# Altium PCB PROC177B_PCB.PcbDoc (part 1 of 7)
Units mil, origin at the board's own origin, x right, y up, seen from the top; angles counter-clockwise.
Board outline 4257.98 x 1561.15 mil, 4 copper layers (Top Layer, Int1 (GND), Int2 (PWR), Bottom Layer), stack 63.572 mil thick; 461 components, 307 nets, 1564 pads, 607 vias.
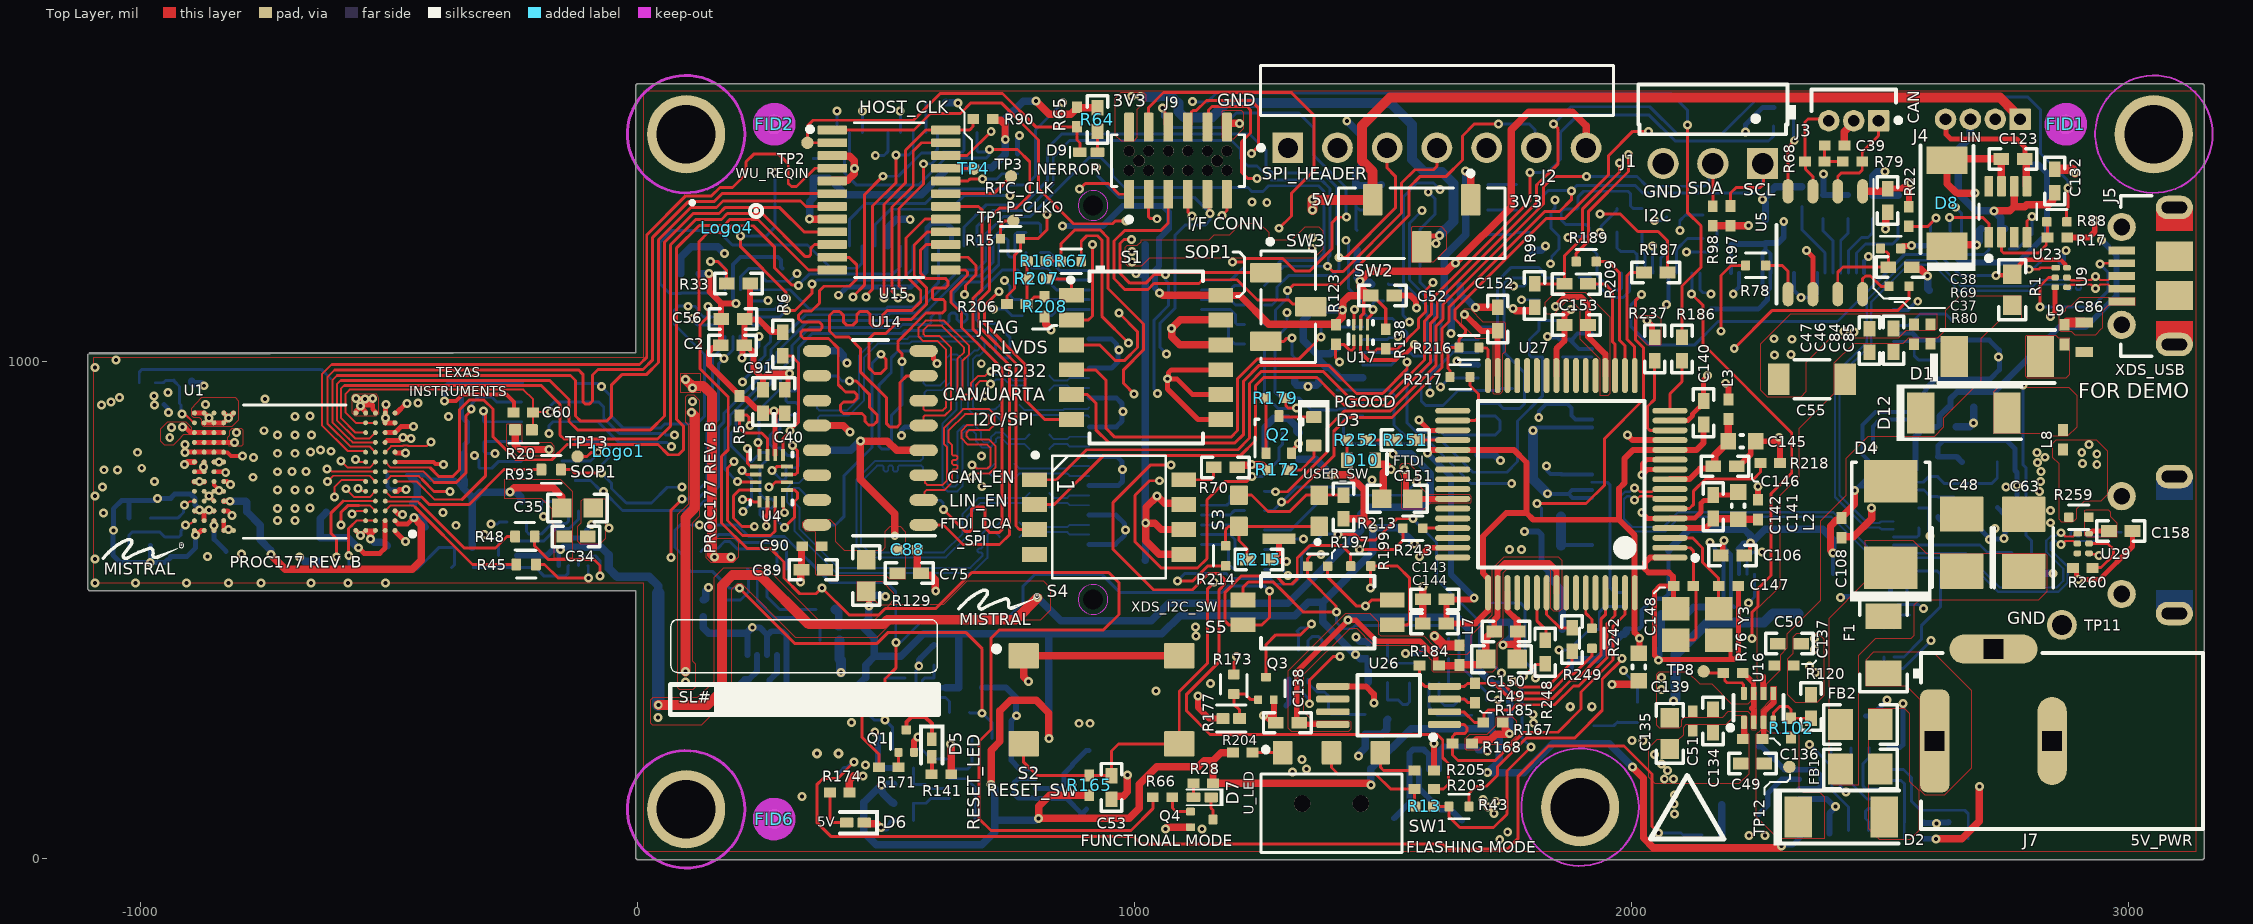
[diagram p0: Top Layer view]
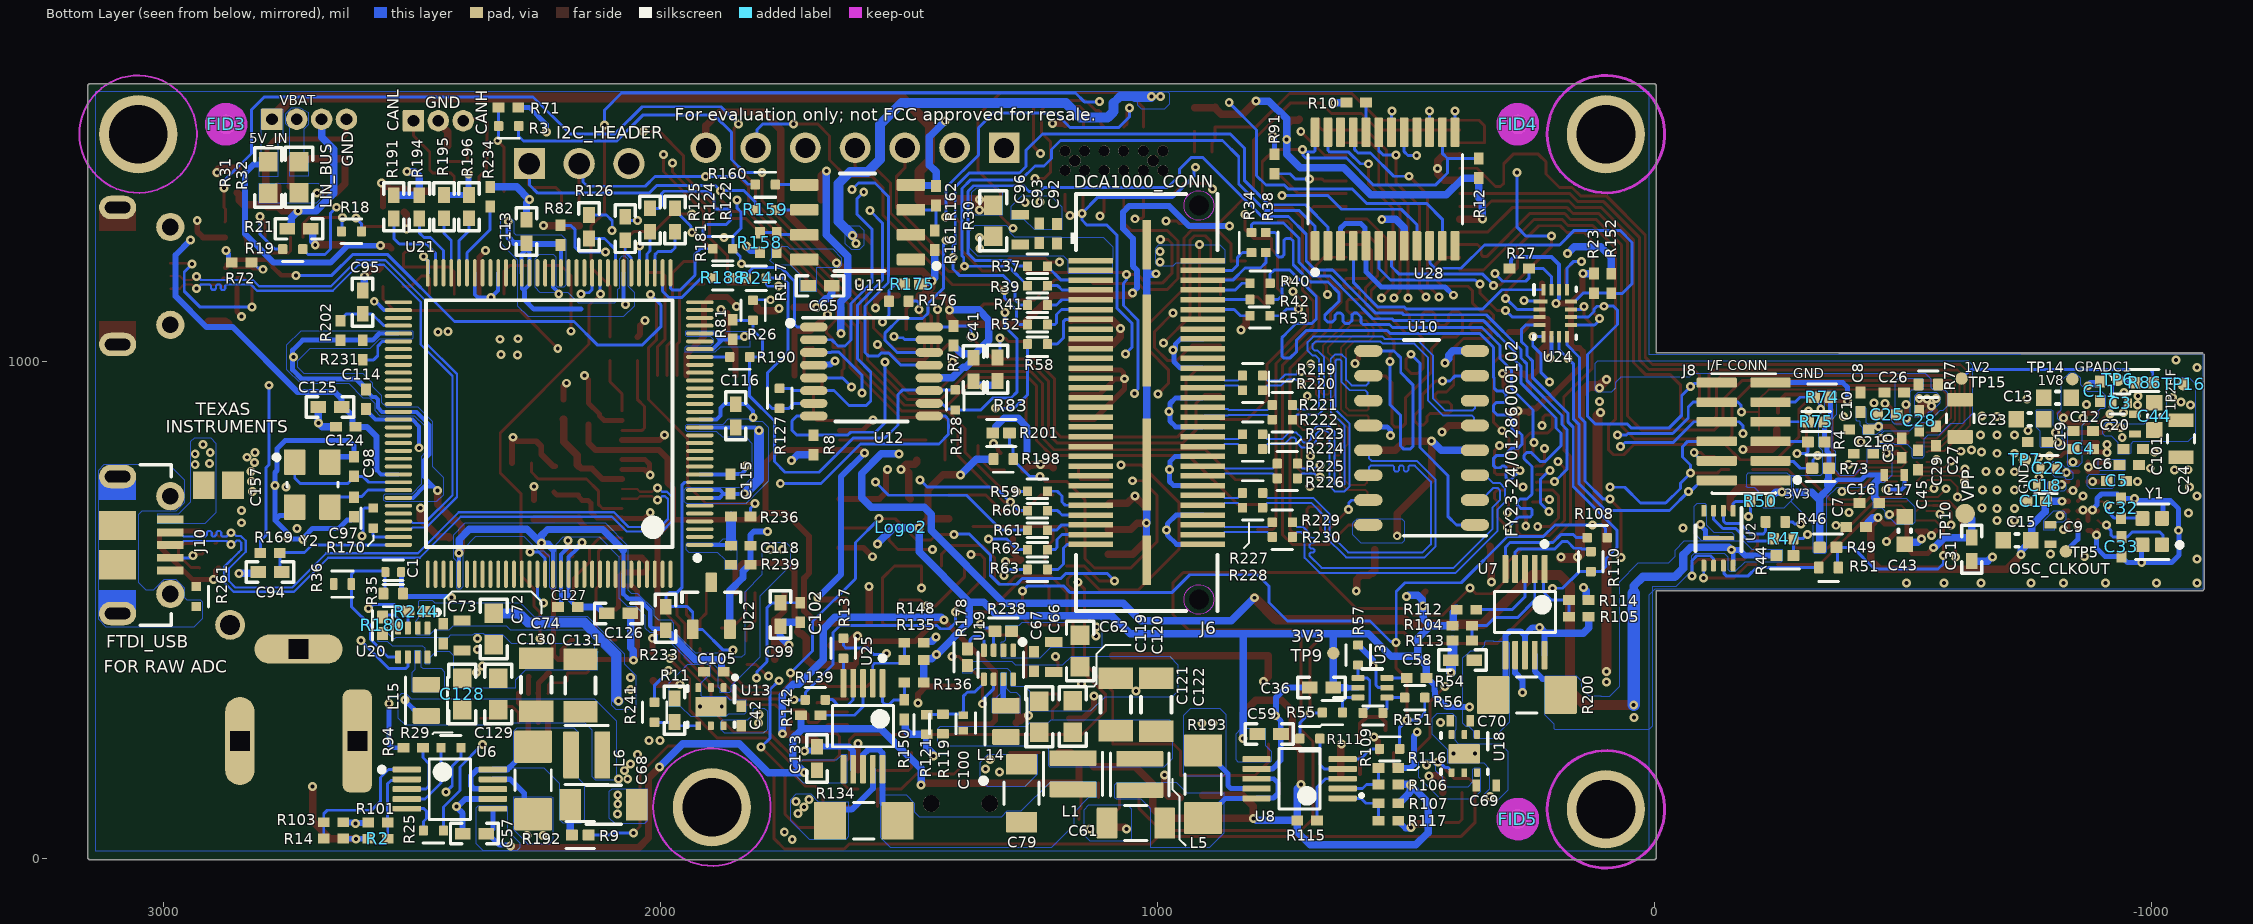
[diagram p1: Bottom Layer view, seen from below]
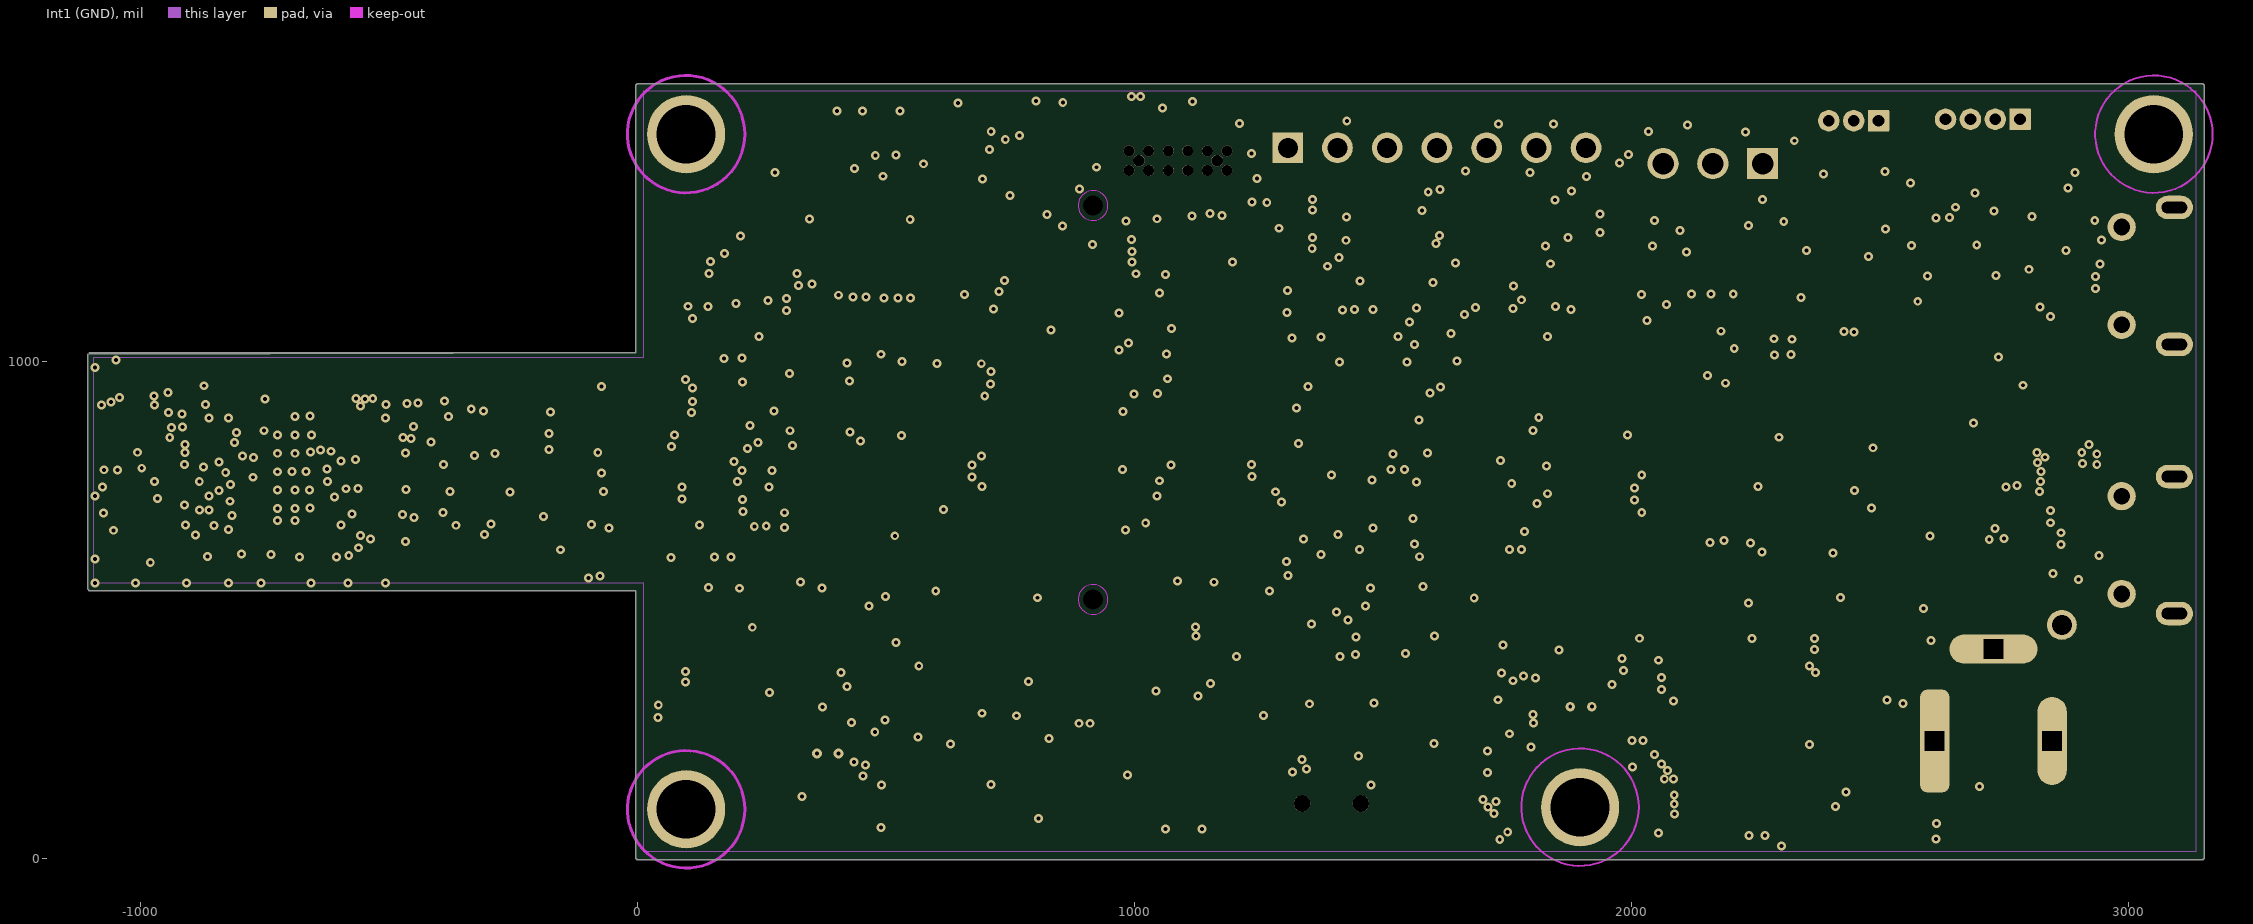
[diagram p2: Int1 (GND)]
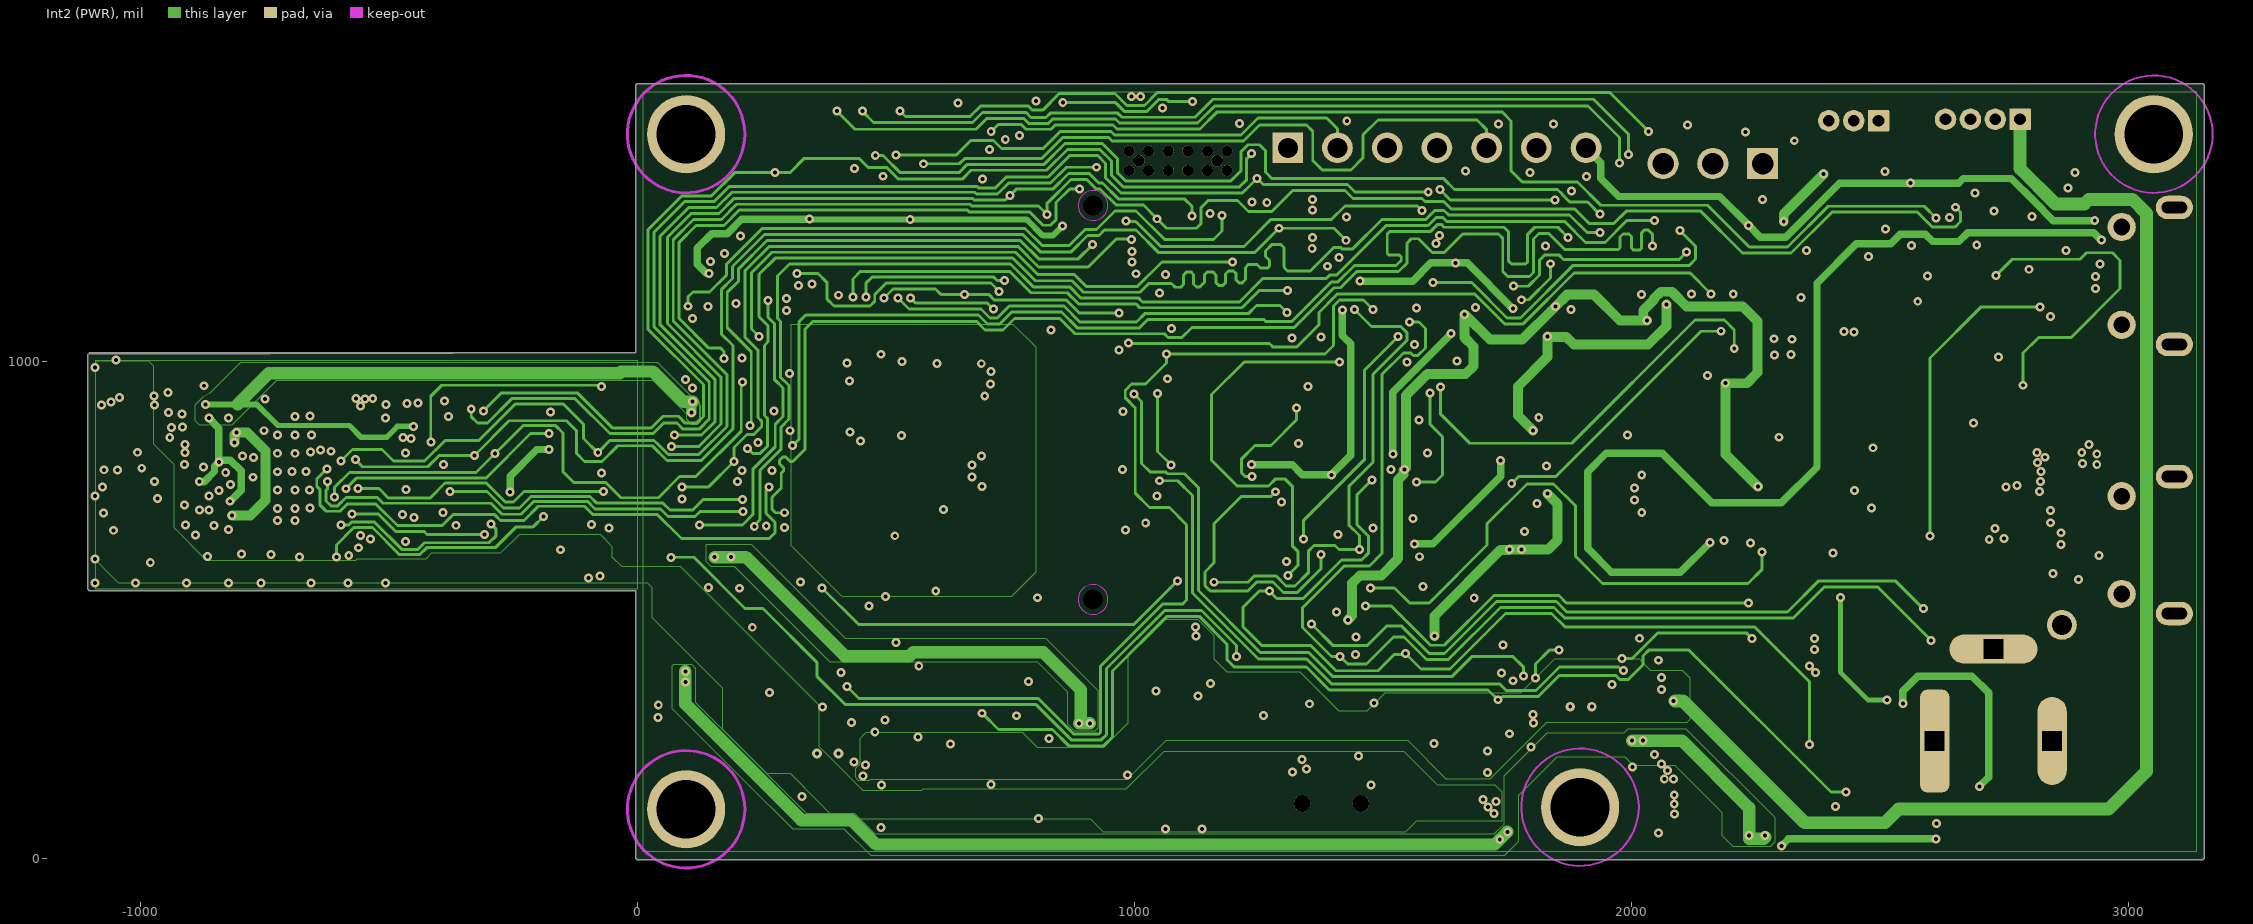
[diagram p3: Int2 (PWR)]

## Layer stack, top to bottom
Top Solder: solder mask 1, Dk 3.5
Top Layer: signal copper 1.85
Dielectric 1: prepreg 1.779, Iteq IT180A Prepreg 106 RC71-NEW, Dk 3.79
Dielectric 2: prepreg 1.779, Iteq IT180A Prepreg 106 RC71-NEW, Dk 3.79
Int1 (GND): signal copper 2.756
Dielectric 3: core 47.244, Iteq IT180A 50 mil core 1/1, Dk 4.28
Int2 (PWR): signal copper 2.756
Dielectric 4: prepreg 1.779, Iteq IT180A Prepreg 106 RC71-NEW, Dk 3.79
Dielectric 5: prepreg 1.779, Iteq IT180A Prepreg 106 RC71-NEW, Dk 3.79
Bottom Layer: signal copper 1.85
Bottom Solder: solder mask 1, Dk 3.5

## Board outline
-1082.65,538.25 -3,538.25 -3.02,0 0,-3.02 3149.61,-3.02 3152.62,0 3152.62,1555.12 3149.49,1558.13 0.14,1558.13 -3.01,1554.89 -3,1016.79 -1082.65,1016.79 -1102.34,1016.79 -3,1016.79 -1105.36,1013.78 -1105.36,541.34 -1102.34,538.24

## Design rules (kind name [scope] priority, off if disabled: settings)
AcuteAngle [All] p0 off: scope1count=1 scope1_0_kind=Board scope1_0_value=Board scope2count=1 scope2_0_kind=Board scope2_0_value=Board commentlength=0 minimum=4.50000000000000E+0001
AcuteAngle [All] p1 off: minimum=4.50000000000000E+0001 checktracksonly=FALSE
AssemblyTestPointUsage [All] p0: scope1count=1 scope1_0_kind=Board scope1_0_value=Board scope2count=1 scope2_0_kind=Board scope2_0_value=Board commentlength=0
AssemblyTestPointUsage [All] p1: valid=2
AssemblyTestpoint [All] p0: scope1count=1 scope1_0_kind=Board scope1_0_value=Board scope2count=1 scope2_0_kind=Board scope2_0_value=Board commentlength=0
BoardOutlineClearance GND_VIA [All] p0 off: scope1count=1 scope1_0_kind=Board scope1_0_value=Board scope2count=1 scope2_0_kind=Board scope2_0_value=Board commentlength=61 gap=2 // Protel DXP Scope 1 Expression Was: IsVia and InNet('GND')
BoardOutlineClearance track_silk [All] p0 off: scope1count=1 scope1_0_kind=Board scope1_0_value=Board scope2count=1 scope2_0_kind=Board scope2_0_value=Board commentlength=90 gap=0 // Protel DXP Scope 1 Expression Was: IsTrack and (OnBottomSilkscreen or OnTopSilkscreen)
BoardOutlineClearance txt [All] p0 off: scope1count=1 scope1_0_kind=Board scope1_0_value=Board scope2count=1 scope2_0_kind=Board scope2_0_value=Board commentlength=89 gap=1 // Protel DXP Scope 1 Expression Was: IsText and (OnBottomSilkscreen or OnTopSilkscreen)
BoardOutlineClearance FAB_TEXT [All] p0 off: scope1count=1 scope1_0_kind=Board scope1_0_value=Board scope2count=1 scope2_0_kind=Board scope2_0_value=Board commentlength=61 gap=0 // Protel DXP Scope 1 Expression Was: WithinRoom('FAB TEXT')
BoardOutlineClearance [All] p0: scope1count=1 scope1_0_kind=Board scope1_0_value=Board scope2count=1 scope2_0_kind=Board scope2_0_value=Board commentlength=0 gap=12
BoardOutlineClearance GND_VIA [IsVia and InNet('GND')] p1: gap=2 ignorepadtopadclearanceinfootprint=FALSE
BoardOutlineClearance track_silk [IsTrack and (OnBottomSilkscreen or OnTopSilkscreen)] p2: gap=0 ignorepadtopadclearanceinfootprint=FALSE
BoardOutlineClearance FAB_TEXT [WithinRoom('FAB TEXT')] p3: gap=0 ignorepadtopadclearanceinfootprint=FALSE
BoardOutlineClearance txt [IsText and (OnBottomSilkscreen or OnTopSilkscreen)] p4: gap=1 ignorepadtopadclearanceinfootprint=FALSE
BoardOutlineClearance [All] p5: gap=12 ignorepadtopadclearanceinfootprint=FALSE except(0: Poly-OutlineEdge)
Clearance Clearance_diff_ext [All] p0 off: scope1count=1 scope1_0_kind=Board scope1_0_value=Board scope2count=1 scope2_0_kind=Board scope2_0_value=Board commentlength=66 gap=6 // Protel DXP Scope 2 Expression Was: OnTopLayer or OnBottomLayer
Clearance BGA_SENSOR [All] p0 off: scope1count=1 scope1_0_kind=Board scope1_0_value=Board scope2count=1 scope2_0_kind=Board scope2_0_value=Board commentlength=59 gap=6 // Protel DXP Scope 1 Expression Was: WithinRoom('sensor')
Clearance "top and bottom" [All] p0 off: scope1count=1 scope1_0_kind=Board scope1_0_value=Board scope2count=1 scope2_0_kind=Board scope2_0_value=Board commentlength=66 gap=6 // Protel DXP Scope 1 Expression Was: OnTopLayer or OnBottomLayer
Clearance "Inner layers" [All] p0 off: scope1count=1 scope1_0_kind=Board scope1_0_value=Board scope2count=1 scope2_0_kind=Net scope2_0_value=GND commentlength=80 gap=6 // Protel DXP Scope 1 Expression Was: OnLayer('L3_SIGNAL 1') OR ('L6_SIGNAL 4')
Clearance Clearance_Keepout [All] p0 off: scope1count=1 scope1_0_kind=Board scope1_0_value=Board scope2count=1 scope2_0_kind=Board scope2_0_value=Board commentlength=48 gap=0 // Protel DXP Scope 1 Expression Was: IsKeepOut
Clearance Same_net [All] p0: scope1count=1 scope1_0_kind=Board scope1_0_value=Board scope2count=1 scope2_0_kind=Board scope2_0_value=Board commentlength=0 gap=0
Clearance Clearance_KO-J5 [All] p0 off: scope1count=1 scope1_0_kind=Board scope1_0_value=Board scope2count=1 scope2_0_kind=Component scope2_0_value=J5 commentlength=60 gap=19.6 // Protel DXP Scope 1 Expression Was: IsKeepOut and IsTrack
Clearance Clearance_BGA [All] p0 off: scope1count=1 scope1_0_kind=Board scope1_0_value=Board scope2count=1 scope2_0_kind=Board scope2_0_value=Board commentlength=57 gap=4 // Protel DXP Scope 1 Expression Was: WithinRoom('BGA1')
Clearance [All] p0: scope1count=1 scope1_0_kind=Board scope1_0_value=Board scope2count=1 scope2_0_kind=Board scope2_0_value=Board commentlength=0 gap=6
Clearance Clearance_Keepout [IsKeepOut] p1: gap=0 ignorepadtopadclearanceinfootprint=TRUE
Clearance BGA_SENSOR [WithinRoom('sensor')] p2: gap=6 ignorepadtopadclearanceinfootprint=TRUE except(0: Text-Hole; 4: Arc-Track Track-Track Track-SMDPad Track-Via; 5: Arc-Arc Arc-SMDPad SMDPad-Via; 5.1: Track-Region SMDPad-SMDPad; 5.6: Via-Region; 7: Arc-Fill Arc-Poly Arc-Region Track-Fill SMDPad-Region THPad-Region; 7.3: Region-Region; 8: SMDPad-Fill SMDPad-Poly THPad-Fill THPad-Poly; 10: Fill-Fill Fill-Poly Fill-Region Poly-Poly Poly-Region; 10.6: Fill-Hole Region-Hole; 11: Poly-Hole; 12: Track-Poly)
Clearance Clearance_diff_ext [InAnyDifferentialPair vs OnTopLayer or OnBottomLayer] p3: gap=6 ignorepadtopadclearanceinfootprint=TRUE except(0: Text-Hole; 4.5: Track-Track; 5: Arc-Arc Arc-Track Arc-SMDPad Track-SMDPad Track-Region; 5.1: SMDPad-SMDPad; 6.2: Region-Region; 7: Arc-Fill Arc-Region Track-Fill; 8: Arc-Poly SMDPad-Fill THPad-Fill Via-Poly Fill-Poly; 10: SMDPad-Poly THPad-Poly Fill-Fill Fill-Region Poly-Region; 11: Fill-Hole Poly-Hole Region-Hole; 12: Track-Poly Poly-Poly)
Clearance [All] p4: gap=6 ignorepadtopadclearanceinfootprint=TRUE except(0: Text-Hole; 5: Arc-Arc Arc-Track Arc-SMDPad Track-SMDPad SMDPad-Region THPad-Region; 5.1: SMDPad-SMDPad; 5.8: Track-Region; 5.9: Via-Region; 6.2: Region-Region; 7: Arc-Fill Arc-Region Track-Fill; 8: Arc-Poly SMDPad-Fill THPad-Fill Via-Poly Fill-Poly; 10: SMDPad-Poly THPad-Poly Fill-Fill Fill-Region Poly-Region; 10.9: Region-Hole; 11: Fill-Hole Poly-Hole; 12: Track-Poly Poly-Poly)
Clearance Clearance_BGA [WithinRoom('BGA1')] p5: gap=4 ignorepadtopadclearanceinfootprint=FALSE except(8: Fill-Fill Fill-Poly Fill-Region Poly-Poly Poly-Region Region-Region; 10: Fill-Hole Poly-Hole Region-Hole)
Clearance "top and bottom" [OnTopLayer or OnBottomLayer] p6: gap=6 ignorepadtopadclearanceinfootprint=TRUE except(5: Arc-Arc Arc-Track Arc-SMDPad Arc-Hole Track-SMDPad Track-Hole SMDPad-Hole THPad-Hole Via-Hole Text-Hole; 5.1: SMDPad-SMDPad; 7: Arc-Fill Arc-Poly Arc-Region Track-Fill Track-Region; 8: Track-Poly SMDPad-Fill SMDPad-Poly SMDPad-Region THPad-Fill THPad-Poly THPad-Region Via-Fill Via-Poly Via-Region Poly-Poly; 10: Fill-Fill Fill-Poly Fill-Region Poly-Region Region-Region; 11: Fill-Hole Poly-Hole Region-Hole)
Clearance Clearance_KO-J5 [IsKeepOut and IsTrack vs InComponent('J5')] p7: gap=19.6 ignorepadtopadclearanceinfootprint=FALSE except(9: SMDPad-SMDPad)
Clearance "Inner layers" [OnLayer('L3_SIGNAL 1') OR ('L6_SIGNAL 4') vs InNet('GND')] p8: gap=6 ignorepadtopadclearanceinfootprint=TRUE except(0: Text-Hole; 5: Arc-Arc Arc-Track Arc-SMDPad Track-Track Track-SMDPad; 5.1: SMDPad-SMDPad; 7: Arc-Fill Arc-Poly Arc-Region Track-Fill Track-Region; 8: SMDPad-Fill SMDPad-Poly SMDPad-Region THPad-Fill THPad-Poly THPad-Region; 10: Fill-Fill Fill-Poly Fill-Region Poly-Region Region-Region; 11: Fill-Hole Poly-Hole Region-Hole; 15: Track-Poly; 20: Poly-Poly)
Clearance Same_net [All] p9: gap=0 ignorepadtopadclearanceinfootprint=TRUE
ComponentClearance ComponentClearance_MatingCon-3D [All] p0 off: scope1count=1 scope1_0_kind=Board scope1_0_value=Board scope2count=1 scope2_0_kind=Board scope2_0_value=Board commentlength=57 gap=0 collisioncheckmode=3 // Protel DXP Scope 2 Expression Was: not InAnyComponent
ComponentClearance "ComponentClearance_WEE Logo" [All] p0: scope1count=1 scope1_0_kind=Component scope1_0_value=Logo4 scope2count=1 scope2_0_kind=Board scope2_0_value=Board commentlength=0 gap=0 collisioncheckmode=3
ComponentClearance ComponentClearance_R77 [All] p0: scope1count=1 scope1_0_kind=Component scope1_0_value=R77 scope2count=1 scope2_0_kind=Component scope2_0_value=Logo1 commentlength=0 gap=0 collisioncheckmode=3
ComponentClearance ComponentClearance_Logo [All] p0: scope1count=1 scope1_0_kind=ComponentClass scope1_0_value=Logo scope2count=1 scope2_0_kind=Board scope2_0_value=Board commentlength=0 gap=0 collisioncheckmode=3
ComponentClearance "ComponentClearance_Mounting Holes_Fiducial Marks" [All] p0: scope1count=1 scope1_0_kind=ComponentClass scope1_0_value=FiducialMark scope2count=1 scope2_0_kind=PadClass scope2_0_value="Mounting Holes PADS" commentlength=0 gap=50 collisioncheckmode=3
ComponentClearance [All] p0: scope1count=1 scope1_0_kind=Board scope1_0_value=Board scope2count=1 scope2_0_kind=Board scope2_0_value=Board commentlength=0 gap=1 collisioncheckmode=3
ComponentClearance ComponentClearance_MatingCon-3D [All vs not InAnyComponent] p1: gap=0 collisioncheckmode=3 verticalgap=0 showdistances=FALSE
ComponentClearance "ComponentClearance_WEE Logo" [InComponent('Logo4')] p2: gap=0 collisioncheckmode=3 verticalgap=0 showdistances=TRUE
ComponentClearance ComponentClearance_R77 [InComponent('R77') vs InComponent('Logo1')] p3: gap=0 collisioncheckmode=3 verticalgap=0 showdistances=TRUE
ComponentClearance ComponentClearance_Logo [InComponentClass('Logo')] p4: gap=0 collisioncheckmode=3 verticalgap=0 showdistances=TRUE
ComponentClearance "ComponentClearance_Mounting Holes_Fiducial Marks" [InComponentClass('FiducialMark') vs InPadClass('Mounting Holes PADS')] p5: gap=50 collisioncheckmode=3 verticalgap=10 showdistances=TRUE
ComponentClearance [All] p6: gap=1 collisioncheckmode=3 verticalgap=10 showdistances=TRUE
DiffPairsRouting 90E [All] p0 off: scope1count=1 scope1_0_kind=Board scope1_0_value=Board scope2count=1 scope2_0_kind=Board scope2_0_value=Board commentlength=69 // Protel DXP Scope 1 Expression Was: InDifferentialPairClass('90E')
DiffPairsRouting 100E [All] p0 off: scope1count=1 scope1_0_kind=Board scope1_0_value=Board scope2count=1 scope2_0_kind=Board scope2_0_value=Board commentlength=70 // Protel DXP Scope 1 Expression Was: InDifferentialPairClass('100E')
DiffPairsRouting 100E [InDifferentialPairClass('100E')] p1: maxlimit=6 minlimit=6 mostfreqgap=6 toplayer_minwidth=4 toplayer_maxwidth=4 toplayer_prefwidth=4 midlayer1_minwidth=4 midlayer1_maxwidth=4 midlayer1_prefwidth=4 midlayer2_minwidth=4 midlayer2_maxwidth=4 midlayer2_prefwidth=4 bottomlayer_minwidth=4 bottomlayer_maxwidth=4 bottomlayer_prefwidth=4 maxuncoupledlength=500
DiffPairsRouting 90E [InDifferentialPairClass('90E')] p2: maxlimit=4.5 minlimit=4.5 mostfreqgap=4.5 toplayer_minwidth=4.5 toplayer_maxwidth=4.5 toplayer_prefwidth=4.5 midlayer1_minwidth=4.5 midlayer1_maxwidth=4.5 midlayer1_prefwidth=4.5 midlayer2_minwidth=4.5 midlayer2_maxwidth=4.5 midlayer2_prefwidth=4.5 bottomlayer_minwidth=4.5 bottomlayer_maxwidth=4.5 bottomlayer_prefwidth=4.5 maxuncoupledlength=500
FabricationTestPointUsage TestPointUsage [All] p0: scope1count=1 scope1_0_kind=Board scope1_0_value=Board scope2count=1 scope2_0_kind=Board scope2_0_value=Board commentlength=0 valid=2 allowmultiple=FALSE
FabricationTestPointUsage TestPointUsage [All] p1: valid=2 allowmultiple=FALSE
FabricationTestpoint Testpoint [All] p0: scope1count=1 scope1_0_kind=Board scope1_0_value=Board scope2count=1 scope2_0_kind=Board scope2_0_value=Board commentlength=0 side=3 testpointundercomponent=TRUE minsize=40 maxsize=100 preferedsize=60 minholesize=0 maxholesize=40 preferedholesize=32 testpointgrid=1
FabricationTestpoint Testpoint [All] p1: side=3 testpointundercomponent=TRUE minsize=40 maxsize=100 preferedsize=60 minholesize=0 maxholesize=40 preferedholesize=32 testpointgrid=1 allowsidetop=TRUE allowsidebottom=TRUE usegrid=TRUE gridtolerance=0.01
FanoutControl Fanout_LCC [All] p0 off: scope1count=1 scope1_0_kind=Board scope1_0_value=Board scope2count=1 scope2_0_kind=Board scope2_0_value=Board commentlength=69 // Protel DXP Scope 1 Expression Was: IsLCC   Fanout_LCC (Default Rule)
FanoutControl Fanout_BGA [All] p0 off: scope1count=1 scope1_0_kind=Board scope1_0_value=Board scope2count=1 scope2_0_kind=Board scope2_0_value=Board commentlength=69 // Protel DXP Scope 1 Expression Was: IsBGA   Fanout_BGA (Default Rule)
FanoutControl Fanout_SOIC [All] p0 off: scope1count=1 scope1_0_kind=Board scope1_0_value=Board scope2count=1 scope2_0_kind=Board scope2_0_value=Board commentlength=71 // Protel DXP Scope 1 Expression Was: IsSOIC   Fanout_SOIC (Default Rule)
FanoutControl Fanout_Default [All] p0: scope1count=1 scope1_0_kind=Board scope1_0_value=Board scope2count=1 scope2_0_kind=Board scope2_0_value=Board commentlength=30 // Fanout_Default (Default Rule)
FanoutControl Fanout_Small [All] p0 off: scope1count=1 scope1_0_kind=Board scope1_0_value=Board scope2count=1 scope2_0_kind=Board scope2_0_value=Board commentlength=84 // Protel DXP Scope 1 Expression Was: (CompPinCount < 5)   Fanout_Small (Default Rule)
FanoutControl Fanout_LCC [IsLCC] p1: bgadir=Out bgaviamode=Centered fanoutstyle=Auto fanoutdirection=Alternating viagrid=1 // Fanout_LCC (Default Rule)
FanoutControl Fanout_BGA [IsBGA] p2: bgadir=Out bgaviamode=Centered fanoutstyle=Auto fanoutdirection=Alternating viagrid=1 // Fanout_BGA (Default Rule)
FanoutControl Fanout_Default [All] p4: bgadir=Out bgaviamode=Centered fanoutstyle=Auto fanoutdirection=Alternating viagrid=1 // Fanout_Default (Default Rule)
FanoutControl Fanout_Small [(CompPinCount < 5)] p5: bgadir=Out bgaviamode=Centered fanoutstyle=Auto fanoutdirection=OutThenIn viagrid=1 // Fanout_Small (Default Rule)
Height Room_Hieght [All] p0 off: scope1count=1 scope1_0_kind=Board scope1_0_value=Board scope2count=1 scope2_0_kind=Board scope2_0_value=Board commentlength=69 // Protel DXP Scope 1 Expression Was: WithinRoom('Room_Hieght 1 MM')
Height Room_Hieght [WithinRoom('Room_Hieght 1 MM')] p1: minheight=0 maxheight=41.34 prefheight=39.37
HoleSize [All] p0: scope1count=1 scope1_0_kind=Board scope1_0_value=Board scope2count=1 scope2_0_kind=Board scope2_0_value=Board commentlength=0 absolutevalues=TRUE maxlimit=280 minlimit=5.9 maxpercent=80.000 minpercent=20.000
HoleSize [All] p1: absolutevalues=TRUE maxlimit=280 minlimit=5.9 maxpercent=80.000 minpercent=20.000
HoleToHoleClearance HoleToHoleClearance_1 [All] p0 off: scope1count=1 scope1_0_kind=Board scope1_0_value=Board scope2count=1 scope2_0_kind=Board scope2_0_value=Board commentlength=57 // Protel DXP Scope 1 Expression Was: WithinRoom('BGA1')
HoleToHoleClearance HoleToHoleClearance_1 [WithinRoom('BGA1')] p1: gap=4 allowstackedmicrovias=FALSE
LayerPairs [All] p0: scope1count=1 scope1_0_kind=Board scope1_0_value=Board scope2count=1 scope2_0_kind=Board scope2_0_value=Board commentlength=0 enforce=TRUE
MatchedLengths DiffPair_MatchedLengths [All] p0 off: scope1count=1 scope1_0_kind=Board scope1_0_value=Board scope2count=1 scope2_0_kind=Board scope2_0_value=Board commentlength=70 tolerance=1000 amplitude=200 gap=20 style=90-Degree // Protel DXP Scope 1 Expression Was: InDifferentialPairClass('100E')
MatchedLengths MatchedLengths_XDSET [All] p0 off: scope1count=1 scope1_0_kind=Board scope1_0_value=Board scope2count=1 scope2_0_kind=Board scope2_0_value=Board commentlength=62 tolerance=2.5 amplitude=200 gap=20 style=90-Degree // Protel DXP Scope 1 Expression Was: InxSignalClass('XDSET')
MatchedLengths MatchedLengths_CAN [All] p0 off: scope1count=1 scope1_0_kind=Board scope1_0_value=Board scope2count=1 scope2_0_kind=Board scope2_0_value=Board commentlength=60 tolerance=2.5 amplitude=200 gap=20 style=90-Degree // Protel DXP Scope 1 Expression Was: InxSignalClass('CAN')
MatchedLengths MatchedLengths_QSPI [All] p0 off: scope1count=1 scope1_0_kind=Board scope1_0_value=Board scope2count=1 scope2_0_kind=Board scope2_0_value=Board commentlength=61 tolerance=200 amplitude=200 gap=20 style=90-Degree // Protel DXP Scope 1 Expression Was: InxSignalClass('QSPI')
MatchedLengths MatchedLengths_RADAR_LVDS [All] p0 off: scope1count=1 scope1_0_kind=Board scope1_0_value=Board scope2count=1 scope2_0_kind=Board scope2_0_value=Board commentlength=67 tolerance=2.5 amplitude=200 gap=20 style=90-Degree // Protel DXP Scope 1 Expression Was: InxSignalClass('RADAR_LVDS')
MatchedLengths MatchedLengths_DCA_T [All] p0 off: scope1count=1 scope1_0_kind=Board scope1_0_value=Board scope2count=1 scope2_0_kind=Board scope2_0_value=Board commentlength=62 tolerance=1000 amplitude=200 gap=20 style=90-Degree // Protel DXP Scope 1 Expression Was: InxSignalClass('DCA_T')
MatchedLengths MatchedLengths_XDS_T [All] p0 off: scope1count=1 scope1_0_kind=Board scope1_0_value=Board scope2count=1 scope2_0_kind=Board scope2_0_value=Board commentlength=62 tolerance=50 amplitude=200 gap=20 style=90-Degree // Protel DXP Scope 1 Expression Was: InxSignalClass('XDS_T')
MatchedLengths MatchedLengths_XDS_DCA_T [All] p0 off: scope1count=1 scope1_0_kind=Board scope1_0_value=Board scope2count=1 scope2_0_kind=Board scope2_0_value=Board commentlength=66 tolerance=5 amplitude=200 gap=20 style=90-Degree // Protel DXP Scope 1 Expression Was: InxSignalClass('XDS_DCA_T')
MatchedLengths MatchedLengths_RADAR_LVDS_DATA [All] p0: scope1count=1 scope1_0_kind=NetClass scope1_0_value=RADAR_LVDS_DATA scope2count=1 scope2_0_kind=Board scope2_0_value=Board commentlength=0 tolerance=5 amplitude=200 gap=20 style=90-Degree
MatchedLengths MatchedLengths_LVDS_D [All] p0: scope1count=1 scope1_0_kind=NetClass scope1_0_value=LVDS_D scope2count=1 scope2_0_kind=Board scope2_0_value=Board commentlength=0 tolerance=5 amplitude=200 gap=20 style=90-Degree
MatchedLengths DiffPair_MatchedLengths [InDifferentialPairClass('100E')] p1: tolerance=1000 checknetsindiffpair=FALSE checkdiffpairvsdiffpair=TRUE checkxsignals=TRUE checkothers=TRUE
MatchedLengths MatchedLengths_LVDS_D [InNetClass('LVDS_D')] p2: tolerance=5 checknetsindiffpair=FALSE checkdiffpairvsdiffpair=TRUE checkxsignals=TRUE checkothers=TRUE
MatchedLengths MatchedLengths_XDS_DCA_T [InxSignalClass('XDS_DCA_T')] p3: tolerance=5 checknetsindiffpair=FALSE checkdiffpairvsdiffpair=TRUE checkxsignals=TRUE checkothers=TRUE
MatchedLengths MatchedLengths_XDSET [InxSignalClass('XDSET')] p4: tolerance=2.5 checknetsindiffpair=FALSE checkdiffpairvsdiffpair=TRUE checkxsignals=TRUE checkothers=TRUE
MatchedLengths MatchedLengths_DCA_T [InxSignalClass('DCA_T')] p5: tolerance=1000 checknetsindiffpair=FALSE checkdiffpairvsdiffpair=TRUE checkxsignals=TRUE checkothers=TRUE
MatchedLengths MatchedLengths_XDS_T [InxSignalClass('XDS_T')] p6: tolerance=50 checknetsindiffpair=FALSE checkdiffpairvsdiffpair=TRUE checkxsignals=TRUE checkothers=TRUE
MatchedLengths MatchedLengths_QSPI [InxSignalClass('QSPI')] p7: tolerance=200 checknetsindiffpair=FALSE checkdiffpairvsdiffpair=TRUE checkxsignals=TRUE checkothers=TRUE
MatchedLengths MatchedLengths_CAN [InxSignalClass('CAN')] p8: tolerance=2.5 checknetsindiffpair=FALSE checkdiffpairvsdiffpair=TRUE checkxsignals=TRUE checkothers=TRUE
MatchedLengths MatchedLengths_RADAR_LVDS_DATA [InNetClass('RADAR_LVDS_DATA')] p9: tolerance=5 checknetsindiffpair=FALSE checkdiffpairvsdiffpair=TRUE checkxsignals=TRUE checkothers=TRUE
MatchedLengths MatchedLengths_RADAR_LVDS [InxSignalClass('RADAR_LVDS')] p10: tolerance=2.5 checknetsindiffpair=FALSE checkdiffpairvsdiffpair=TRUE checkxsignals=TRUE checkothers=TRUE
MinimumAnnularRing MinimumAnnularRing_ThermalPadVias [All] p0 off: scope1count=1 scope1_0_kind=Board scope1_0_value=Board scope2count=1 scope2_0_kind=Board scope2_0_value=Board commentlength=63 minimumring=3.9 // Protel DXP Scope 1 Expression Was: IsVia and InAnyComponent
MinimumAnnularRing [All] p0: scope1count=1 scope1_0_kind=Board scope1_0_value=Board scope2count=1 scope2_0_kind=Board scope2_0_value=Board commentlength=0 minimumring=3.9
MinimumAnnularRing MinimumAnnularRing_ThermalPadVias [IsVia and InAnyComponent] p1: minimumring=3.9
MinimumAnnularRing [All] p2: minimumring=3.9
MinimumSolderMaskSliver MinimumSolderMaskSliver_Logo [All] p0: scope1count=1 scope1_0_kind=ComponentClass scope1_0_value=Logo scope2count=1 scope2_0_kind=ComponentClass scope2_0_value=Logo commentlength=0
MinimumSolderMaskSliver [All] p0: scope1count=1 scope1_0_kind=Board scope1_0_value=Board scope2count=1 scope2_0_kind=Board scope2_0_value=Board commentlength=0
MinimumSolderMaskSliver MinimumSolderMaskSliver_Logo [InComponentClass('Logo') vs InComponentClass('Logo')] p1: minsoldermaskwidth=0.7
MinimumSolderMaskSliver [All] p2: minsoldermaskwidth=3.5
NetAntennae [All] p0: scope1count=1 scope1_0_kind=Board scope1_0_value=Board scope2count=1 scope2_0_kind=Board scope2_0_value=Board commentlength=0
PasteMaskExpansion [All] p0: scope1count=1 scope1_0_kind=Board scope1_0_value=Board scope2count=1 scope2_0_kind=Board scope2_0_value=Board commentlength=0 expansion=0
PlaneClearance [All] p0: scope1count=1 scope1_0_kind=Board scope1_0_value=Board scope2count=1 scope2_0_kind=Board scope2_0_value=Board commentlength=0 clearance=20
PlaneConnect [All] p0: scope1count=1 scope1_0_kind=Board scope1_0_value=Board scope2count=1 scope2_0_kind=Board scope2_0_value=Board commentlength=0 planeconnectstyle=Relief reliefexpansion=10 reliefentries=4 reliefconductorwidth=10 reliefairgap=10
PlaneConnect [All] p1: planeconnectstyle=Relief reliefexpansion=10 reliefentries=4 reliefconductorwidth=10 reliefairgap=10
PolygonConnect [All] p0: scope1count=1 scope1_0_kind=Board scope1_0_value=Board scope2count=1 scope2_0_kind=Board scope2_0_value=Board commentlength=0 connectstyle=Direct reliefconductorwidth=10 reliefentries=4 polygonreliefangle="90 Angle"
PolygonConnect [All] p1: connectstyle=Direct reliefconductorwidth=10 reliefentries=4 polygonreliefangle="90 Angle" airgapwidth=10
RoomDefinition "FAB TEXT" [All] p0 off: scope1count=1 scope1_0_kind=Board scope1_0_value=Board scope2count=1 scope2_0_kind=Board scope2_0_value=Board commentlength=44 region_x1=12378871 region_y1=6167368 region_x2=21198871 region_y2=7897368 confinementstyle=ConfineIn // Protel DXP Scope 1 Expression Was: False
RoomDefinition sensor [All] p0 off: scope1count=1 scope1_0_kind=Board scope1_0_value=Board scope2count=1 scope2_0_kind=Board scope2_0_value=Board commentlength=44 region_x1=4715465 region_y1=21223934 region_x2=16538871 region_y2=25949133 confinementstyle=ConfineIn // Protel DXP Scope 1 Expression Was: False
RoomDefinition "FAB TEXT" [False vs False] p1: confinementstyle=ConfineIn formatcopy=TRUE lockcomponents=FALSE outline -336,-791.4 546,-791.4 546,-964.4 -336,-964.4
RoomDefinition sensor [False vs False] p2: confinementstyle=ConfineIn formatcopy=TRUE lockcomponents=FALSE outline -1102.34,1013.78 80,1013.78 80,541.26 -1102.34,541.26
RoutingCorners [All] p0: scope1count=1 scope1_0_kind=Board scope1_0_value=Board scope2count=1 scope2_0_kind=Board scope2_0_value=Board commentlength=0 cornerstyle=45-Degree minsetback=100 maxsetback=100
RoutingLayers [All] p0: scope1count=1 scope1_0_kind=Board scope1_0_value=Board scope2count=1 scope2_0_kind=Board scope2_0_value=Board commentlength=0 top layer=Automatic mid layer 1=Automatic mid layer 2=Automatic bottom layer=Automatic
RoutingPriority [All] p0: scope1count=1 scope1_0_kind=Board scope1_0_value=Board scope2count=1 scope2_0_kind=Board scope2_0_value=Board commentlength=0
RoutingTopology [All] p0: scope1count=1 scope1_0_kind=Board scope1_0_value=Board scope2count=1 scope2_0_kind=Board scope2_0_value=Board commentlength=0 topology=Shortest
RoutingVias ThermalPadVias [All] p0 off: scope1count=1 scope1_0_kind=Board scope1_0_value=Board scope2count=1 scope2_0_kind=Board scope2_0_value=Board commentlength=63 holewidth=7.87 width=19.68 viastyle="Through Hole" minholewidth=5 minwidth=13 maxholewidth=12.99 maxwidth=23.62 // Protel DXP Scope 1 Expression Was: IsVia and InAnyComponent
RoutingVias [All] p0: scope1count=1 scope1_0_kind=Board scope1_0_value=Board scope2count=1 scope2_0_kind=Board scope2_0_value=Board commentlength=0 holewidth=12.2 width=22.4 viastyle="Through Hole" minholewidth=5.9 minwidth=14 maxholewidth=20 maxwidth=40
RoutingVias ThermalPadVias [IsVia and InAnyComponent] p1: holewidth=7.87 width=19.68 viastyle="Through Hole" minholewidth=5 minwidth=13 maxholewidth=12.99 maxwidth=23.62
RoutingVias [All] p2: holewidth=12.2 width=22.4 viastyle="Through Hole" minholewidth=5.9 minwidth=14 maxholewidth=20 maxwidth=40
ShortCircuit [All] p0: scope1count=1 scope1_0_kind=Board scope1_0_value=Board scope2count=1 scope2_0_kind=Board scope2_0_value=Board commentlength=0 allowed=FALSE
SilkToBoardRegionClearance [All] p0 off: scope1count=1 scope1_0_kind=Board scope1_0_value=Board scope2count=1 scope2_0_kind=Board scope2_0_value=Board commentlength=130 // Protel DXP Scope 1 Expression Was: Not ((IsComment or IsDesignator) And (Hide <> 'False')) and not InRegion(1000,500,4000,800)
SilkToBoardRegionClearance [Not ((IsComment or IsDesignator) And (Hide <> 'False')) and not InRegion(1000,500,4000,800)] p1:
SilkToSilkClearance [All] p0: scope1count=1 scope1_0_kind=Board scope1_0_value=Board scope2count=1 scope2_0_kind=Board scope2_0_value=Board commentlength=0
SilkToSilkClearance [All] p1: silktosilkclearance=3
SilkToSolderMaskClearance SilkToSolderMaskClearance_OutLine [All] p0 off: scope1count=1 scope1_0_kind=Board scope1_0_value=Board scope2count=1 scope2_0_kind=Board scope2_0_value=Board commentlength=65 // Protel DXP Scope 1 Expression Was: istrack and InAnyComponent
SilkToSolderMaskClearance SilkscreenOverComponentPads [All] p0 off: scope1count=1 scope1_0_kind=Board scope1_0_value=Board scope2count=1 scope2_0_kind=Board scope2_0_value=Board commentlength=44 // Protel DXP Scope 1 Expression Was: IsPad
SilkToSolderMaskClearance SilkToSolderMaskClearance_OutLine [istrack and InAnyComponent] p1: minsilkscreentomaskgap=0 clearancetoexposedcopper=FALSE
SilkToSolderMaskClearance SilkscreenOverComponentPads [IsPad] p2: minsilkscreentomaskgap=3 clearancetoexposedcopper=FALSE
SolderMaskExpansion [All] p0: scope1count=1 scope1_0_kind=Board scope1_0_value=Board scope2count=1 scope2_0_kind=Board scope2_0_value=Board commentlength=0 expansion=0
SolderMaskExpansion [All] p1: expansion=0 istentingtop=FALSE
UnRoutedNet [All] p0: scope1count=1 scope1_0_kind=Board scope1_0_value=Board scope2count=1 scope2_0_kind=Board scope2_0_value=Board commentlength=0
UnRoutedNet [All] p1: checkbadconnections=TRUE
UnpouredPolygon [All] p0: scope1count=1 scope1_0_kind=Board scope1_0_value=Board scope2count=1 scope2_0_kind=Board scope2_0_value=Board commentlength=0
Width [All] p0: scope1count=1 scope1_0_kind=Board scope1_0_value=Board scope2count=1 scope2_0_kind=Board scope2_0_value=Board commentlength=0 maxlimit=40 minlimit=4 preferedwidth=5.9
Width [All] p1: maxlimit=40 minlimit=4 preferedwidth=5.9 midlayer1_minwidth=5.9 midlayer2_minwidth=5.9 bottomlayer_minwidth=5.9 minimp=50.000000 maximp=50.000000 favimp=50.000000
12 further rules are at their usual default settings.

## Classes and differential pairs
component class PROC177B_Analog_MUX_SPI: C56 R10 R12 U28
component class PROC177B_I2C_SPI_Connector: J1 J2 J9 mx R83 SW2 SW3
component class PROC177B_FTDI: C138 C139 C140 C141 C142 C143 C144 C145 C146 C147 C148 C149 C150 C151 C152 C153 C157 C158 D10 J10 L2 L3 L7 m mx R99 R167 R168 R184 R185 R186 R187 R189 R209 R216 R217 R218 R237 R242 R243 R248 R249 R251 R252 R259 R260 R261 U26 U27 U29 Y3
net class RADAR_LVDS_DATA: RADAR_LVDS_CLK RADAR_LVDS_DATA0 RADAR_LVDS_DATA1 RADAR_LVDS_DATA2 RADAR_LVDS_DATA3 RADAR_LVDS_FRCLK
net class LVDS_D: LVDS_CLK_RTC_CLKIN_TP LVDS_D0_LIN_PHY_RX LVDS_D1_XDS_UARTA_RX_CAN_RX LVDS_D2_XDS_UARTA_TX_CAN_TX LVDS_D3_nERROR_LED_WD_TP LVDS_FRCLK_HOST_CLK_TP
net class POWER: 3V3_LDO_EN 5V_IN 5V_IN_USB 5V_REG CONN_5V PMIC_CLKOUT PMIC_CLKOUT_LIN_PHY_TX_SOP1 REG_1V2 REG_1V8 REG_OUT_1V2 REG_OUT_1V8 REG_PG REG_RF_1V2 SW_PR1
component class PROC177B_XDS110_Interface: C42 C94 C95 C97 C98 C99 C102 C105 C106 C108 C113 C114 C115 C116 C118 C124 C125 C126 C127 R11 R24 R26 R81 R82 R122 R124 R125 R126 R169 R170 R181 R188 R190 R191 R194 R195 R196 R197 R199 R202 R231 R233 R234 R236 R239 R241 S5 U13 U21 U22 Y2
component class PROC177B_DC_Regulators: C1 C61 C62 C66 C67 C68 C69 C70 C72 C73 C74 C79 C100 C119 C120 C121 C122 C128 C129 C130 C131 L1 L5 L6 L14 L15 Q3 R9 R35 R36 R119 R121 R173 R175 R176 R177 R178 R180 R198 R201 R238 R244 TP9 TP11 U18 U19 U20
net class Regions: 5V_IN 5V_IN_USB GND NetD1_2 NetD2_2 XTALP
component class Logo: Logo1
component class FiducialMark: FID1 FID2 FID3 FID4 FID5 FID6
component class PROC177B_Decoupling_caps_QSPI_Flash_: C4 C5 C6 C7 C8 C9 C10 C11 C12 C13 C14 C15 C16 C17 C18 C19 C20 C21 C22 C23 C24 C25 C26 C27 C28 C29 C30 C34 C35 C44 C45 C101 R44 R45 R46 R47 R48 R49 R50 R51 U2
component class PROC177B_EVM_Hardware: FID1 FID2 FID3 FID4 FID5 FID6 Logo1 Logo2 LOGO3 Logo4 ZZ1 ZZ2 ZZ3 ZZ4 ZZ5
component class Header: J1
component class PROC177B_xWRL6432AoP_Chip: C3 C31 C32 C33 C43 C60 J8 ms R4 R20 R73 R74 R75 R77 R86 R93 TP5 TP6 TP7 TP10 TP13 TP14 TP15 TP16 U1 Y1
component class PROC177B_CAN_LIN_PHY_Interface: C37 C38 C39 C123 C132 D8 J3 J4 R3 R17 R18 R19 R21 R22 R31 R32 R68 R69 R71 R78 R79 R80 R88 U5 U23
component class PROC177B_LVDS_Driver: C75 C88 C89 C90 C91 R90 R91 R129 TP2 TP3 TP4 U10 U14 U15
component class PROC177B_Temp_Current_sensors_EPROM: C36 C57 C58 C59 C65 C133 R2 R14 R25 R29 R54 R55 R56 R57 R94 R97 R98 R101 R103 R104 R105 R106 R107 R108 R109 R110 R111 R112 R113 R114 R115 R116 R117 R134 R135 R136 R137 R139 R142 R148 R150 R151 R157 R158 R159 R160 R161 R162 R192 R193 R200 U3 U6 U7 U8 U11 U25
component class AssemblyNote: ZZ1 ZZ2 ZZ3 ZZ4 ZZ5
component class PROC177B_USB_PWR_DC_Jack_Switch: C46 C47 C48 C49 C50 C51 C55 C63 C84 C85 C86 C134 C135 C136 C137 D1 D2 D3 D4 D6 D12 F1 FB1 FB2 FL1 FL2 J5 J7 L8 L9 LD1 Q2 R1 R72 R76 R102 R120 R172 R174 R179 TP8 TP12 U9 U16
component class PROC177B_DCA1000_Connector_Reset: C52 C53 C92 C93 C96 D5 D7 D9 J6 LD2 LD4 mx Q1 Q4 R28 R30 R34 R37 R38 R39 R40 R41 R42 R52 R53 R58 R59 R60 R61 R62 R63 R64 R65 R66 R123 R138 R141 R165 R171 R213 R214 R215 R219 R220 R221 R222 R223 R224 R225 R226 R227 R228 R229 R230 S2 S3 U17
component class PROC177B_Analog_Mux_SOP_Ctrl: C2 C40 C41 R5 R6 R7 R8 R13 R15 R16 R23 R27 R33 R43 R67 R70 R127 R128 R152 R203 R204 R205 R206 R207 R208 S1 S4 SW1 TP1 U4 U12 U24
differential pair FTDI_USB: +FTDI_USBD_P -FTDI_USBD_N
differential pair CAN: +CANL -CANH
differential pair LVDS_FRCLK: +NetJ6_26 -NetJ6_28
differential pair LVDS_FRCLK_DP8: +RADAR_LVDS_FRCLKP -RADAR_LVDS_FRCLKM
differential pair LVDS_CLK: +NetJ6_46 -NetJ6_44
differential pair LVDS_CLK_DP7: +RADAR_LVDS_CLKP -RADAR_LVDS_CLKM
differential pair LVDS_3: +NetJ6_32 -NetJ6_34
differential pair LVDS_3_DP6: +RADAR_LVDS_3P -RADAR_LVDS_3M
differential pair LVDS_2: +NetJ6_38 -NetJ6_40
differential pair LVDS_2_DP5: +RADAR_LVDS_2P -RADAR_LVDS_2M
differential pair LVDS_1: +NetJ6_50 -NetJ6_52
differential pair LVDS_1_DP4: +RADAR_LVDS_1P -RADAR_LVDS_1M
differential pair LVDS_0: +NetJ6_56 -NetJ6_58
differential pair LVDS_0_DP3: +RADAR_LVDS_0P -RADAR_LVDS_0M
differential pair " ": +XDSET_1_DP -XDSET_1_DM

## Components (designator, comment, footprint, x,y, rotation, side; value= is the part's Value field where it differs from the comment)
C1 "GJM1555C1H100FB01D" FP-GJM1555C1H100FB01D_0402-MFG 2538,575.6 r0 bottom
C2 "C0402C104K8RACTU" 0402 191.79,1032 r0 top
C3 "GRM155C80J105KA12D" FP-GRM155C80J105KA12D_0402-MFG -936.51,915.11 r0 bottom
C4 "CL05B224KO5NNNC" 0402L -861.69,823.27 r0 bottom
C5 "CL05B224KO5NNNC" 0402L -928.89,759.16 r0 bottom
C6 "C1005X7R1H473K050BB" 0402L -954.29,791.28 r180 bottom
C7 "CL05B224KO5NNNC" 0402L -404.95,666.31 r180 bottom
C8 "CL05B224KO5NNNC" 0402L -413.7,917.2 r270 bottom
C9 "GRM155C81C225KE11D" 0402S -796.05,651.26 r90 bottom
C10 "CL05B224KO5NNNC" 0402L -410.75,862.73 r180 bottom
C11 "CL05B224KO5NNNC" 0402L -895.64,939.59 r270 bottom
C12 "CL05B224KO5NNNC" 0402L -861.75,859.54 r0 bottom
C13 "GRM188C81A106MA73D" 0603L -809.83,926.37 r0 bottom
C14 "CL05B224KO5NNNC" 0402L -767.2,718.18 r180 bottom
C15 "GRM188C81A106MA73D" 0603L -728.49,639.33 r0 bottom
C16 "CL05B224KO5NNNC" 0402L -431.54,714.38 r180 bottom
C17 "GRM155C81C225KE11D" 0402S -481.85,770.72 r0 bottom
C18 "GRM155C80J105KA12D" FP-GRM155C80J105KA12D_0402-MFG -783.92,748.92 r180 bottom
C19 "CL05B224KO5NNNC" 0402L -769.73,837.09 r180 bottom
C20 "GRM155C81C225KE11D" 0402S -965.93,873.42 r270 bottom
C21 "CL05B224KO5NNNC" 0402L -419.92,813.77 r180 bottom
C22 "GRM155C80J105KA12D" FP-GRM155C80J105KA12D_0402-MFG -791.25,784.21 r180 bottom
C23 "GRM188C81A106MA73D" 0603L -754.48,882.83 r0 bottom
C24 "GRM21BR71C475KE51L" FP-GRM21BR71C475KE51L_0805-MFG -1058.5,843.8 r90 bottom
C25 "CL05B224KO5NNNC" 0402L -466.71,892.5 r180 bottom
C26 "CL05B224KO5NNNC" 0402L -481.51,937 r180 bottom
C27 "GRM21BR71C475KE51L" FP-GRM21BR71C475KE51L_0805-MFG -614.09,884.93 r90 bottom
C28 "CL05B224KO5NNNC" 0402L -531.9,880.26 r270 bottom
C29 "CL05B224KO5NNNC" 0402L -565.75,849.51 r90 bottom
C30 "C0402C103K4RACTU" 0402L -496.85,825.26 r270 bottom
C31 "C1005X7R1H104K050BE" 0402 -637.54,621.5 r270 bottom
C32 "GJM1555C1H4R7BB01D" 0402L -937.91,703.76 r270 bottom
C33 "GJM1555C1H4R7BB01D" 0402L -938.64,626.35 r90 bottom
C34 "C1005X7R1H104K050BE" 0402 -123.28,647.05 r0 top
C35 "CL10B105KO8NFNC" 0603 -119.98,704.58 r180 top
C36 "GCM155R71H104KE02D" 0402 670.48,343.24 r0 bottom
C37 "C0402C104K8RACTU" 0402 2540.57,1189.11 r180 top
C38 "C0402C104K8RACTU" 0402 2515.6,1323.38 r90 top
C39 "GCM155R71H472KA37D" 0402L 2409,1433.6 r180 top
C40 "C0402C104K8RACTU" 0402 296.84,918.94 r90 top
C41 "C0402C104K8RACTU" 0402 1370.83,983.24 r270 bottom
C42 "C1005X7S1A225K050BC" 0402_065L 1837.69,286.05 r90 bottom
C43 "GRM188C81A106MA73D" 0603L -502.75,659.1 r270 bottom
C44 "GRM188C81A106MA73D" 0603L -1004.41,889.04 r90 bottom
C45 "C0402C103K4RACTU" 0402L -529.26,801.31 r270 bottom
C46 "GRM155R61A106ME11D" 0402 2527.55,1042.09 r270 top
C47 "GRM155R61A106ME11D" 0402 2479.01,1041.64 r90 top
C48 "T491B476K010AT" 3528-21 2664.63,634.94 r90 top
C49 "GCM155R71H104KE02D" 0402 2243.72,190.48 r180 top
C50 "GCM155R71H104KE02D" 0402 2317.97,431.63 r180 top
C51 "GRT155C81A105KE01D" 0402L 2123.57,276.24 r270 top
C52 "GCM155R71H104KE02D" 0402 1499.21,1131.87 r180 top
C53 "GCM155R71H104KE02D" 0402 954,142.6 r270 top
C55 "GRM31CR61A476KE15L" 1206_180 2363.38,963.49 r180 top
C56 "GCM155R71H104KE02D" 0402 192.53,1084.61 r0 top
C57 "GCM155R71H104KE02D" 0402 2374.77,49.43 r0 bottom
C58 "GCM155R71H104KE02D" 0402 386.7,398.47 r0 bottom
C59 "GCM155R71H104KE02D" 0402 775.79,249.69 r180 bottom
C60 "CL05B224KO5NNNC" 0402L -228.99,896.44 r0 top
C61 "GRM31CR70J226ME19K" FP-GRM31CR70J226ME19K_1206-MFG 1044.03,70.8 r180 bottom
C62 "GRM188C81A106MA73D" 0603 1156.35,416.75 r270 bottom
C63 "T491B476K010AT" 3528-21 2789.33,634.39 r90 top
C65 "GCM155R71H104KE02D" 0402 1679.36,1151.54 r180 bottom
C66 "GRM188R71C474KA88D" 0603S 1208.99,404.57 r270 bottom
C67 "GRM1555C1H471JA01D" 0402L 1248.84,395.61 r270 bottom
C68 "GRM31CR60J476ME19L" 1206_180 2114.72,107.45 r0 bottom
C69 "GRM155C81C225KE11D" 0402S 339.16,146.27 r0 bottom
C70 "GRM155C81C225KE11D" 0402S 391.76,276.58 r180 bottom
C72 "GRM188C81A106MA73D" 0603 2335.86,460.98 r270 bottom
C73 "GRM188R71C474KA88D" 0603S 2399.71,448.21 r270 bottom
C74 "GRM1555C1H471JA01D" 0402L 2437.19,451.83 r270 bottom
C75 "GCM155R71H104KE02D" 0402 547.26,573.55 r0 top
C79 "GRM31CR70J226ME19K" FP-GRM31CR70J226ME19K_1206-MFG 1274,130.6 r270 bottom
C84 "GCM155C71A474KE36D" 0402L 2568.88,1053.8 r90 top
C85 "GCM155R71C224KE02D" 0402L 2601.76,1054.73 r270 top
C86 "GRT188R61A106KE13D" 0603S 2910.89,1048.17 r90 top
C88 "GCM155R71E103KA37D" 0402L 543.72,620.74 r0 top
C89 "GCM155R71H104KE02D" 0402 354.19,580.27 r180 top
C90 "GCM155R71E103KA37D" 0402L 351.56,627.8 r180 top
C91 "GCM155R71H104KE02D" 0402 253.09,918.94 r90 top
C92 "GCM155C71A474KE36D" 0402L 1202.77,1256.36 r90 bottom
C93 "GRT155C81A105KE01D" 0402L 1238.41,1257.18 r90 bottom
C94 "C0402C104K8RACTU" 0402 2786,575.6 r0 bottom
C95 "C0402C104K8RACTU" 0402 2599.45,1118.65 r270 bottom
C96 "GRT188R61A106KE13D" 0603S 1276.77,1264.52 r270 bottom
C97 "CC0402DRNPO9BN8R0" 0402L 2616.98,706.75 r90 bottom
C98 "CC0402DRNPO9BN8R0" 0402L 2616.98,787.95 r270 bottom
C99 "C0402C104K8RACTU" 0402 1759.12,490.29 r90 bottom
C100 "GJM1555C1H100FB01D" FP-GJM1555C1H100FB01D_0402-MFG 1391.2,272.06 r90 bottom
C101 "CL05B224KO5NNNC" 0402L -962.32,823.13 r0 bottom
C102 "GCM155R71E103KA37D" 0402L 1719.12,494.23 r90 bottom
C105 "C1005X7S1A225K050BC" 0402_065L 1893.01,375.07 r180 bottom
C106 "C0402C104K8RACTU" 0402 2203.44,608.87 r0 top
C108 "GRT155C81A105KE01D" 0402L 2423,664.6 r270 top
C113 "C0402C104K8RACTU" 0402 2269.89,1260.99 r270 bottom
C114 "GRT155C81A105KE01D" 0402L 2592.89,923.38 r270 bottom
C115 "GCM155R71E103KA37D" 0402L 1859.31,752.89 r90 bottom
C116 "C0402C104K8RACTU" 0402 1848.96,890 r270 bottom
C118 "GCM155R71E103KA37D" 0402L 1839,628.6 r0 bottom
C119 "GRM188C81A106MA73D" 0603 1238.56,284.57 r90 bottom
C120 "GRM188C81A106MA73D" 0603 1170.74,285.07 r90 bottom
C121 "C3216X6S1A226M160AB" 1206_180L 1084.38,309.27 r270 bottom
C122 "C3216X6S1A226M160AB" 1206_180L 1003.13,309 r270 bottom
C123 "GCM155R71H104KE02D" 0402 2768,1406.74 r0 top
C124 "C1005X7S1A225K050BC" 0402_065L 2633.47,868.02 r180 bottom
C125 "C0402C104K8RACTU" 0402 2665.14,907.54 r180 bottom
C126 "C0402C104K8RACTU" 0402 2085.08,492.65 r0 bottom
C127 "GRT155C81A105KE01D" 0402L 2186.69,505.45 r0 bottom
C128 "GRM188C81A106MA73D" 0603 2398.91,330.26 r90 bottom
C129 "GRM188C81A106MA73D" 0603 2326.75,330.26 r90 bottom
C130 "C3216X6S1A226M160AB" 1206_180L 2250.46,348.82 r270 bottom
C131 "C3216X6S1A226M160AB" 1206_180L 2161.46,347.44 r270 bottom
C132 "885012005063" 0402 2851.75,1362.4 r90 top
C133 "GCM155R71H104KE02D" 0402 1685.69,200.71 r90 bottom
C134 "GCM155R71H104KE02D" 0402 2164.38,276.25 r270 top
C135 "GRM188Z71A106MA73D" 0603 2077.15,251.31 r270 top
C136 "GRT155C81A105KE01D" 0402L 2244,239.6 r180 top
C137 "GRT155C81A105KE01D" 0402L 2307,387.6 r0 top
C138 "C0402C104K8RACTU" 0402 1308,272.6 r180 top
C139 "C1608X7S1A475K080AC" 0603L 2015.1,384.8 r270 top
C140 "C0402C104K8RACTU" 0402 2145.41,896.26 r90 top
C141 "C1608X7S1A475K080AC" 0603L 2214.74,709.19 r90 top
C142 "C0402C104K8RACTU" 0402 2164.74,707.22 r270 top
C143 "C0402C104K8RACTU" 0402 1604.4,520.77 r180 top
C144 "C0402C104K8RACTU" 0402 1604.25,472.34 r180 top
C145 "C1608X7S1A475K080AC" 0603L 2222.39,838.85 r0 top
C146 "C0402C104K8RACTU" 0402 2188.53,788.54 r180 top
C147 "GCM1555C1H8R0DA16D" 0402L 2195.43,547.51 r0 top
C148 "GCM1555C1H8R0DA16D" 0402L 2104.92,547.51 r180 top
C149 "GCM188R71C105KA64D" 0603 1738.57,400.73 r180 top
C150 "C0402C104K8RACTU" 0402 1747.8,456.06 r0 top
C151 "GCM188R71C105KA64D" 0603 1529.11,723.04 r0 top
C152 "C0402C104K8RACTU" 0402 1731.16,1084.69 r90 top
C153 "C0402C104K8RACTU" 0402 1889.06,1072.47 r180 top
C157 "CL21B106KOQNNNE" 0805L 2889.83,750.46 r180 bottom
C158 "C0402C104K8RACTU" 0402 2984.65,658.22 r0 top
D1 "PMEG3020EP,115" SOD-128 2736.44,1009.5 r0 top
D2 "PMEG3020EP,115" SOD-128 2422.41,83.16 r0 top
D3 "TLMY1000-GS08" TLMx1000_Yellow 1361.24,858.87 r90 top
D4 "SZP6SMB6.8AT3G" SMB 2522,671.6 r90 top
D5 "APHHS1005CGCK" APHHS1005_Green 592.69,221.68 r90 top
D6 "APHHS1005CGCK" APHHS1005_Green 439.08,71.69 r0 top
D7 "APHHS1005CGCK" APHHS1005_Green 1136.94,122.48 r0 top
D8 "PMEG3020EP,115" SOD-128 2635,1317.6 r90 top
D9 "APHHS1005SURCK" APHHS1005_Red 908.35,1420.33 r180 top
D10 "TLMY1000-GS08" TLMx1000_Yellow 1456.4,800.77 r0 top
D12 "PMEG3020EP,115" SOD-128 2668.99,896.02 r0 top
F1 "32V, 5A" 1206 2507.4,429.46 r270 top
FB1 "BLM21PG300SH1D" 0805_HV 2460.75,179.55 r0 top
FB2 "BLM21PG300SH1D" 0805_HV 2460.75,269.12 r0 top
FID1 "Fiducial" Fiducial10-20 2874.02,1476.38 r90 top locked
FID2 "Fiducial" Fiducial10-20 275.58,1476.39 r90 top locked
FID3 "Fiducial" Fiducial10-20 2874.02,1476.38 r180 bottom locked
FID4 "Fiducial" Fiducial10-20 275.58,1476.39 r90 bottom locked
FID5 "Fiducial" Fiducial10-20 275.59,78.74 r180 bottom locked
FID6 "Fiducial" Fiducial10-20 275.59,78.74 r90 top locked
J1 "61300311021" Wurth_61300311021 2163.91,1397.45 r180 top locked
J2 "0022288072" FP-0022288072_HDR7-MFG 1608.83,1544.36 r0 top locked
J3 "M50-3930342" FP-M50-3930342_HDR3-MFG 2447.23,1522.93 r180 top
J4 "M50-3930442" FP-M50-3930442_HDR4-Recommended_Land_Pattern 2707.04,1525.96 r180 top
J5 "105017-0001" CONN_105017-0001 3039.37,1171.38 r90 top
J6 "QSH-030-01-L-D-A" Samtec_QSH-030-01-X-D-A 1022.21,916.8 r180 bottom locked
J7 "PJ-002AH" CUI_PJ-002AH 2728.35,235.81 r0 top
J8 "BC050-12A-K0-0200-0160-0480-LB" FP-BC050-12A-K0-0200-0160-0480-LB_HDR12-MFG -178.72,858.45 r90 bottom
J9 "BC084-12-A-0390-L-C" FP-BC084-12-A-0390-L-C_CONN_RCPT12-MFG 1088.05,1403.29 r0 top locked
J10 "105017-0001" CONN_105017-0001 3039.37,629.99 r270 bottom locked
L1 "LQM2MPZR10MJHL" "FP-LQM2MPZR10MJHL_0806 (2016)-MFG" 1170.43,169.85 r270 bottom
L2 "BLM15HG601SN1D" 0402L 2254.74,701.32 r270 top
L3 "BLM15HG601SN1D" 0402L 2195.5,903.19 r270 top
L5 "LQM2MPZR10MJHL" "FP-LQM2MPZR10MJHL_0806 (2016)-MFG" 1036.11,168.47 r270 bottom
L6 "LQM2MPZR10MJHL" "FP-LQM2MPZR10MJHL_0806 (2016)-MFG" 2148.78,207.73 r0 bottom
L7 "BLM15HG601SN1D" 0402L 1654.28,408.56 r270 top
L8 "BLM15PD300SZ1D" 0402L 2868.49,841.86 r90 top
L9 "BLM15PD300SZ1D" 0402L 2871.65,1053.41 r270 top
L14 "DFE201210U-R47M=P2" "FP-DFE201210U-R47M=P2_0805 (2012)-MFG" 1305.48,275.45 r270 bottom
L15 "DFE201210U-R47M=P2" "FP-DFE201210U-R47M=P2_0805 (2012)-MFG" 2471.34,317.76 r270 bottom
Logo1 "Texas Instruments" TI_Stacked_Overlay_Small -37.24,818.74 r0 top
Logo2 "CE Mark" CE_Mark_5mm 1516.26,665.79 r180 bottom
LOGO3 "FCC disclaimer" FCC_disclaimer 1664.62,4635.57 r180 bottom (schematic designator Logo3)
Logo4 "WEEE logo" WEEE_Minimum 180.88,1268.11 r90 top
Q1 "SSM3K35AMFV,L3F" FP-SSM3K35AMFV,L3F_SOT-723-MFG 541.43,235.6 r90 top
Q2 "BSS123W-7-F" SOT-323 1290.91,852.23 r90 top
Q3 "SSM3K35AMFV,L3F" FP-SSM3K35AMFV,L3F_SOT-723-MFG 1265,341.6 r90 top
Q4 "SSM3K35AMFV,L3F" FP-SSM3K35AMFV,L3F_SOT-723-MFG 1135.92,78 r0 top
R1 "MCT06030Z0000ZP500" 0603 2766,1143.6 r270 top
R2 "CRCW040210K0FKED" 0402L 2568.71,39.05 r0 bottom
R3 "ERJ-2GE0R00X" FP-ERJ-2GE0R00X_0402-MFG 2305.78,1472.96 r0 bottom
R4 "RC0402FR-0710KL" FP-RC0402FR-0710KL_0402-IPC_B -324.72,837.53 r180 bottom
R5 "CRCW040210K0FKED" 0402L 205.72,910.41 r90 top
R6 "CRCW04024K70JNED" 0402 293,1034.6 r270 top
R7 "CRCW040210K0FKED" 0402L 1410.82,1051.2 r270 bottom
R8 "CRCW040210K0FKED" 0402L 1692.31,831.48 r270 bottom
R9 "RC0402FR-0710KL" FP-RC0402FR-0710KL_0402-IPC_B 2161.73,46.65 r180 bottom
R10 "CRCW040210K0FKED" 0402L 600.71,1520.36 r0 bottom
R11 "CRCW0402100KFKED" 0402 1971.93,297.59 r270 bottom
R12 "CRCW040210K0FKED" 0402L 354.19,1387.88 r90 bottom
R13 "CRCW0402750RFKED" 0402L 1583.42,104.1 r180 top
R14 "CRCW040210K0FKED" 0402L 2658,39.82 r180 bottom
R15 "ERJ-2GE0R00X" FP-ERJ-2GE0R00X_0402-MFG 751.09,1246.42 r180 top
R16 "CRCW0402750RFKED" 0402L 804.01,1201.3 r180 top
R17 "CRCW040210K0FKED" 0402L 2857.02,1248.69 r0 top
R18 "ERJ-2GE0R00X" FP-ERJ-2GE0R00X_0402-MFG 2622.02,1260.98 r0 bottom
R19 "ERJ-2GE0R00X" FP-ERJ-2GE0R00X_0402-MFG 2740.1,1225.35 r0 bottom
R20 "RC0402FR-0710KL" FP-RC0402FR-0710KL_0402-IPC_B -228.79,861.86 r180 top
R21 "CRCW04021K00FKED" 0402 2727.38,1266.23 r180 bottom
R22 "CRCW040210K0FKED" 0402L 2558.1,1290.91 r90 top
R23 "CRCW040210K0FKED" 0402L 122.49,1156.44 r270 bottom
R24 "ERJ-2GE0R00X" FP-ERJ-2GE0R00X_0402-MFG 1807.46,1166.95 r0 bottom
R25 "ERJ-2GE0R00X" FP-ERJ-2GE0R00X_0402-MFG 2457,55.6 r180 bottom
R26 "ERJ-2GE0R00X" FP-ERJ-2GE0R00X_0402-MFG 1814.16,1102.37 r90 bottom
R27 "CRCW040210K0FKED" 0402L 272.7,1186.6 r0 bottom
R28 "ERJ-2GEJ511X" 0402L 1138.72,151 r0 top
R29 "ERJ-2GE0R00X" FP-ERJ-2GE0R00X_0402-MFG 2421.9,222.2 r180 bottom
R30 "MCT06030Z0000ZP500" 0603 1330.65,1282.48 r270 bottom
R31 "MCT06030Z0000ZP500" 0603 2789.07,1369.2 r270 bottom
R32 "MCT06030Z0000ZP500" 0603 2727.6,1369.96 r270 bottom
R33 "CRCW04024K70JNED" 0402 203.73,1156.14 r180 top
R34 "ERJ-2GE0R00X" FP-ERJ-2GE0R00X_0402-MFG 811.41,1238.54 r90 bottom
R35 "RC0402JR-070RP" FP-RC0402JR-070RP_0402-MFG 2537.99,532.44 r0 bottom
R36 "CRCW040240K2FKEDC" FP-CRCW040240K2FKEDC_0402-MFG 2640,551.6 r180 bottom
R37 "ERJ-2GE0R00X" FP-ERJ-2GE0R00X_0402-MFG 1242.01,1191.07 r180 bottom
R38 "ERJ-2GE0R00X" FP-ERJ-2GE0R00X_0402-MFG 782.6,1238.77 r90 bottom
R39 "ERJ-2GE0R00X" FP-ERJ-2GE0R00X_0402-MFG 1242.01,1151.87 r180 bottom
R40 "ERJ-2GE0R00X" FP-ERJ-2GE0R00X_0402-MFG 794.15,1156.72 r180 bottom
R41 "ERJ-2GE0R00X" FP-ERJ-2GE0R00X_0402-MFG 1242.01,1112.68 r180 bottom
R42 "ERJ-2GE0R00X" FP-ERJ-2GE0R00X_0402-MFG 794.28,1123.93 r180 bottom
R43 "ERJ-2GE0R00X" FP-ERJ-2GE0R00X_0402-MFG 1653.28,104.1 r180 top
R44 "RC0402FR-0710KL" FP-RC0402FR-0710KL_0402-IPC_B -261.69,608.86 r0 bottom
R45 "RT0402FRE0733R2L" FP-RT0402FRE0733R2L_0402-MFG -223.34,591.06 r180 top
R46 "RT0402FRE0733R2L" FP-RT0402FRE0733R2L_0402-MFG -242.5,676.58 r0 bottom
R47 "RT0402FRE0733R2L" FP-RT0402FRE0733R2L_0402-MFG -259.28,642.85 r0 bottom
R48 "RT0402FRE0733R2L" FP-RT0402FRE0733R2L_0402-MFG -225.79,647.29 r180 top
R49 "RC0402FR-0710KL" FP-RC0402FR-0710KL_0402-IPC_B -348.59,625.44 r0 bottom
R50 "RC0402FR-1047K5L" FP-RC0402FR-1047K5L_0402-MFG -212.01,717.93 r0 bottom
R51 "RT0402FRE0733R2L" FP-RT0402FRE0733R2L_0402-MFG -349.43,584.82 r180 bottom
R52 "ERJ-2GE0R00X" FP-ERJ-2GE0R00X_0402-MFG 1242.01,1073.49 r180 bottom
R53 "ERJ-2GE0R00X" FP-ERJ-2GE0R00X_0402-MFG 794.35,1091.37 r180 bottom
R54 "CRCW040210K0FKED" 0402L 479.26,362.69 r180 bottom
R55 "ERJ-2GE0R00X" FP-ERJ-2GE0R00X_0402-MFG 648.64,293.12 r180 bottom
R56 "ERJ-2GE0R00X" FP-ERJ-2GE0R00X_0402-MFG 483.05,323.15 r0 bottom
R57 "ERJ-2GE0R00X" FP-ERJ-2GE0R00X_0402-MFG 597,408.84 r90 bottom
R58 "ERJ-2GE0R00X" FP-ERJ-2GE0R00X_0402-MFG 1242.01,1034.29 r180 bottom
R59 "ERJ-2GE0R00X" FP-ERJ-2GE0R00X_0402-MFG 1242.01,738.31 r180 bottom
R60 "ERJ-2GE0R00X" FP-ERJ-2GE0R00X_0402-MFG 1242.01,699.12 r180 bottom
R61 "ERJ-2GE0R00X" FP-ERJ-2GE0R00X_0402-MFG 1242.01,659.92 r180 bottom
R62 "ERJ-2GE0R00X" FP-ERJ-2GE0R00X_0402-MFG 1242.01,620.73 r180 bottom
R63 "ERJ-2GE0R00X" FP-ERJ-2GE0R00X_0402-MFG 1242.01,581.08 r180 bottom
R64 "CRCW0402220RJNED" 0402 925.84,1486.09 r90 top
R65 "CRCW040210K0FKED" 0402L 884.63,1491.13 r270 top
R66 "ERJ-2GEJ511X" 0402L 1057,122.6 r180 top
R67 "ERJ-2GE0R00X" FP-ERJ-2GE0R00X_0402-MFG 873.23,1200.7 r180 top
R68 "CRCW040261R9FKED" 0402L 2368.79,1401.45 r180 top
R69 "ERJ-2GE0R00X" FP-ERJ-2GE0R00X_0402-MFG 2521.49,1226.67 r0 top
R70 "CRCW04021K00FKED" 0402 1183.3,786.36 r0 top
R71 "CRCW040210K0FKED" 0402L 2306.28,1510.51 r0 bottom
R72 "CRCW040210K0FKED" 0402L 2843,1198.6 r180 bottom
R73 "WR04X1003FTL" FP-WR04X1003FTL_0402-IPC_B -333.49,784.56 r180 bottom
R74 "WR04X1003FTL" FP-WR04X1003FTL_0402-IPC_B -336.61,927.39 r180 bottom
R75 "RC0402FR-0710KL" FP-RC0402FR-0710KL_0402-IPC_B -324.51,877.74 r180 bottom
R76 "CRCW040210K0FKED" 0402L 2204.61,372.62 r0 top
R77 "RC0402JR-070RP" FP-RC0402JR-070RP_0402-MFG -550.08,953.21 r180 bottom
R78 "ERJ-2GE0R00X" FP-ERJ-2GE0R00X_0402-MFG 2249.94,1192.52 r0 top
R79 "CRCW040261R9FKED" 0402L 2444.87,1401.45 r180 top
R80 "ERJ-2GE0R00X" FP-ERJ-2GE0R00X_0402-MFG 2538.58,1150.59 r180 top
R81 "CRCW040210K0FKED" 0402L 1855,1063.6 r270 bottom
R82 "CRCW040210K0FKED" 0402L 2201.44,1253.44 r270 bottom
R83 "CRCW04021K00FKED" 0402 1322.56,983.8 r90 bottom
R86 "RC0402FR-071KL" FP-RC0402FR-071KL_0402-IPC_B -985.39,956.6 r180 bottom
R88 "ERJ-2GE0R00X" FP-ERJ-2GE0R00X_0402-MFG 2856,1280.21 r180 top
R90 "CRCW040210K0FKED" 0402L 695.76,1487.02 r180 top
R91 "CRCW040210K0FKED" 0402L 765.35,1396.73 r90 bottom
R93 "RT0402FRE0733R2L" FP-RT0402FRE0733R2L_0402-MFG -172.96,781.9 r180 top
R94 "CRCW040210K0FKED" 0402L 2497.71,222.27 r180 bottom
R97 "CRCW040210K0FKED" 0402L 2199.4,1292.25 r270 top
R98 "CRCW040210K0FKED" 0402L 2163.94,1291.86 r270 top
R99 "CRCW0402100KFKED" 0402 1805.44,1131.87 r270 top
R101 "CRCW040210K0FKED" 0402L 2568.71,71.79 r180 bottom
R102 "CRCW040210K0FKED" 0402L 2321.22,261.96 r270 top
R103 "CRCW040210K0FKED" 0402L 2658,72.6 r0 bottom
R104 "CRCW040210K0FKED" 0402L 387.45,467.79 r0 bottom
R105 "CRCW040210K0FKED" 0402L 153,485.6 r180 bottom
R106 "CRCW040210K0FKED" 0402L 536,148.6 r180 bottom
R107 "CRCW040210K0FKED" 0402L 536,110.6 r180 bottom
R108 "ERJ-2GE0R00X" FP-ERJ-2GE0R00X_0402-MFG 116.01,644.91 r180 bottom
R109 "ERJ-2GE0R00X" FP-ERJ-2GE0R00X_0402-MFG 533.56,219.86 r180 bottom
